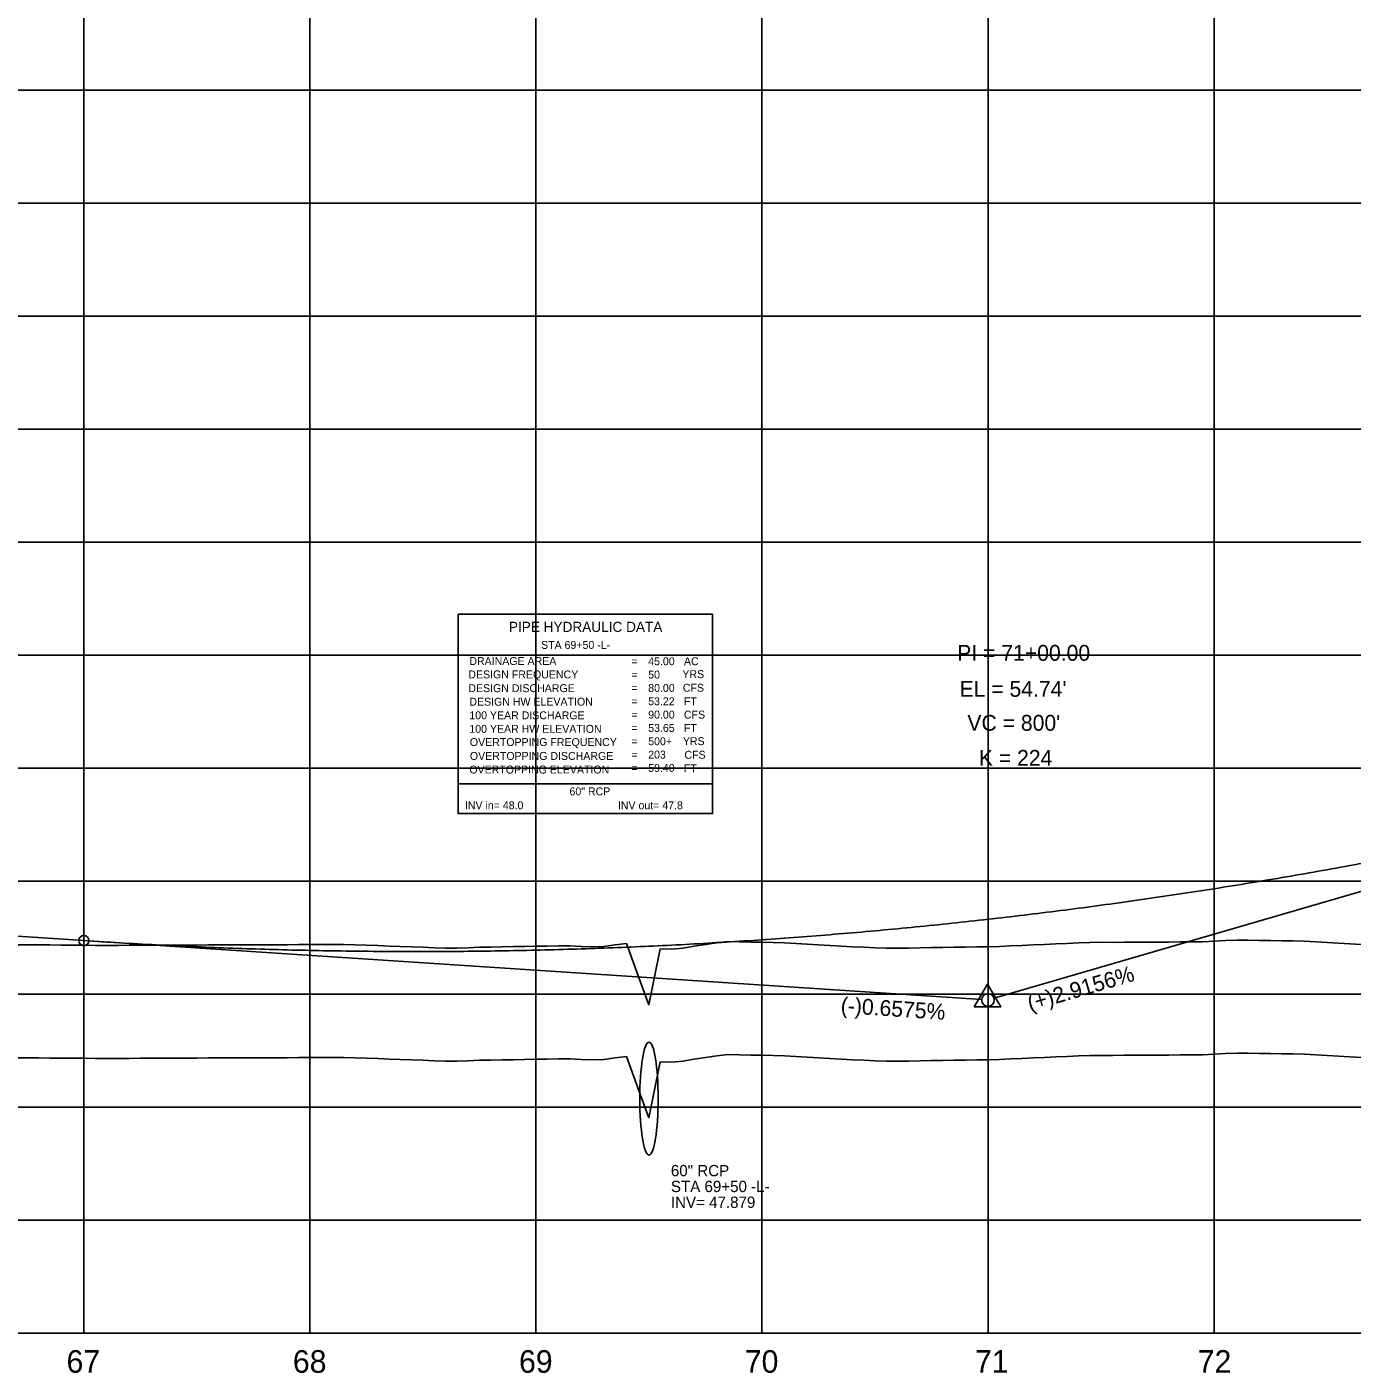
# Model space of a CAD drawing. Extents: x 2345490 to 2445302, y 465165 to 573888.
# Drawn here: x 2386996 to 2387583, y 564259 to 564854 of the extents above; entities that cross this region are included whole.
import ezdxf

# ---------------------------------------------------------------- set-up
doc = ezdxf.new("R2010")
doc.units = 0
for name, color, linetype in [('Old_Level_1', 7, 'Continuous'), ('Old_Level_2', 7, 'Continuous'), ('Old_Level_3', 7, 'Continuous'), ('Old_Level_4', 7, 'Continuous'), ('Old_Level_57', 7, 'Continuous'), ('Old_Level_62', 7, 'Continuous'), ('Old_Level_63', 7, 'Continuous')]:
    doc.layers.add(name, color=color, linetype=linetype)

msp = doc.modelspace()

# ---------------------------------------------------------------- linework, layer by layer
at = {"layer": 'Old_Level_1'}
for points in [[(2386991.5425, 564398.43875), (2386996.5425, 564398.3915), (2387001.5425, 564398.344), (2387006.5425, 564398.29675), (2387011.5425, 564398.24925), (2387016.5425, 564398.202), (2387021.5425, 564398.1545), (2387026.5425, 564398.10725), (2387031.5425, 564398.10625), (2387036.5425, 564398.1245), (2387041.5425, 564398.14725), (2387046.5425, 564398.16975), (2387051.5425, 564398.19225), (2387056.5425, 564398.21475), (2387061.5425, 564398.23725), (2387066.5425, 564398.26), (2387071.5425, 564398.2825), (2387076.5425, 564398.305), (2387081.5425, 564398.3275), (2387086.5425, 564398.346), (2387091.5425, 564398.36275), (2387096.5425, 564398.3795), (2387101.5425, 564398.3965), (2387106.5425, 564398.41325), (2387111.5425, 564398.4305), (2387116.5425, 564398.44875), (2387121.5425, 564398.46675), (2387126.5425, 564398.48475), (2387131.5425, 564398.50275), (2387136.5425, 564398.51525), (2387141.5425, 564398.39725), (2387146.5425, 564398.21075), (2387151.5425, 564398.0245), (2387156.5425, 564397.838), (2387161.5425, 564397.6515), (2387166.5425, 564397.465), (2387171.5425, 564397.27875), (2387176.5425, 564397.09225), (2387181.5425, 564396.90575), (2387186.5425, 564396.8655), (2387191.5425, 564397.10875), (2387196.5425, 564397.2735), (2387201.5425, 564397.36825), (2387206.5425, 564397.4635), (2387211.5425, 564397.55925), (2387216.5425, 564397.6555), (2387221.5425, 564397.75225), (2387226.5425, 564397.84975), (2387231.5425, 564397.9475), (2387236.5425, 564397.87625), (2387241.5425, 564397.678), (2387246.5425, 564397.47975), (2387251.5425, 564397.64325), (2387256.5425, 564398.29725), (2387261.5425, 564398.9515), (2387266.5425, 564385.04125), (2387271.5425, 564371.88275), (2387276.5425, 564396.56725), (2387281.5425, 564396.42575), (2387286.5425, 564396.9605), (2387291.5425, 564397.74525), (2387296.5425, 564398.53), (2387301.5425, 564399.3145), (2387306.5425, 564399.83925), (2387311.5425, 564399.72525), (2387316.5425, 564399.6115), (2387321.5425, 564399.498), (2387326.5425, 564399.38475), (2387331.5425, 564399.212), (2387336.5425, 564398.92425), (2387341.5425, 564398.6365), (2387346.5425, 564398.34875), (2387351.5425, 564398.06125), (2387356.5425, 564397.77375), (2387361.5425, 564397.49475), (2387366.5425, 564397.276), (2387371.5425, 564397.05725)], [(2387371.5425, 564397.05725), (2387376.5425, 564396.8385), (2387381.5425, 564396.87825), (2387386.5425, 564396.959), (2387391.5425, 564397.03975), (2387396.5425, 564397.121), (2387401.5425, 564397.2025), (2387406.5425, 564397.28425), (2387411.5425, 564397.3665), (2387416.5425, 564397.449), (2387421.5425, 564397.5425), (2387426.5425, 564397.69525), (2387431.5425, 564397.913), (2387436.5425, 564398.131), (2387441.5425, 564398.34925), (2387446.5425, 564398.56825), (2387451.5425, 564398.7875), (2387456.5425, 564399.0075), (2387461.5425, 564399.20475), (2387466.5425, 564399.36525), (2387471.5425, 564399.47475), (2387476.5425, 564399.455), (2387481.5425, 564399.4885), (2387486.5425, 564399.5215), (2387491.5425, 564399.55425), (2387496.5425, 564399.587), (2387501.5425, 564399.619), (2387506.5425, 564399.651), (2387511.5425, 564399.68275), (2387516.5425, 564399.714), (2387521.5425, 564400.02025), (2387526.5425, 564400.3435), (2387531.5425, 564400.4925), (2387536.5425, 564400.40725), (2387541.5425, 564400.32225), (2387546.5425, 564400.23725), (2387551.5425, 564400.15225), (2387556.5425, 564400.0675), (2387561.5425, 564399.98275), (2387566.5425, 564399.7175), (2387571.5425, 564399.40875), (2387576.5425, 564399.10025), (2387581.5425, 564398.7915), (2387586.5425, 564398.51675)]]:
    msp.add_lwpolyline(points, dxfattribs=at)
at = {"layer": 'Old_Level_2'}
for p, q in [((2387821.5425, 564540.556), (2387424.18275, 564424.7035)), ((2386871.5425, 564460.0965), (2387021.5425, 564450.234)), ((2387021.5425, 564450.234), (2387418.7985, 564424.11425))]:
    msp.add_line(p, q, dxfattribs=at)
msp.add_lwpolyline([(2387415.38575, 564420.8655), (2387427.12825, 564420.8655), (2387421.25725, 564430.99125)], close=True, dxfattribs=at)
for centre, radius in [((2387021.5425, 564450.234), 2.25), ((2387421.5425, 564423.934), 2.75)]:
    msp.add_circle(centre, radius, dxfattribs=at)
msp.add_spline([(2387021.5425, 564450.234), (2387037.5425, 564449.239), (2387053.5425, 564448.3585), (2387069.5425, 564447.5925), (2387085.5425, 564446.9405), (2387101.5425, 564446.403), (2387117.5425, 564445.98), (2387133.5425, 564445.67125), (2387149.5425, 564445.47675), (2387165.5425, 564445.3965), (2387181.5425, 564445.43075), (2387197.5425, 564445.57925), (2387213.5425, 564445.84225), (2387229.5425, 564446.2195), (2387245.5425, 564446.711), (2387261.5425, 564447.317), (2387277.5425, 564448.037), (2387293.5425, 564448.87175), (2387309.5425, 564449.8205), (2387325.5425, 564450.88375), (2387341.5425, 564452.0615), (2387357.5425, 564453.35325), (2387373.5425, 564454.7595), (2387389.5425, 564456.28025), (2387405.5425, 564457.91525), (2387421.5425, 564459.6645), (2387437.5425, 564461.528), (2387453.5425, 564463.506), (2387469.5425, 564465.59825), (2387485.5425, 564467.805), (2387501.5425, 564470.126), (2387517.5425, 564472.56125), (2387533.5425, 564475.11075), (2387549.5425, 564477.77475), (2387565.5425, 564480.553), (2387581.5425, 564483.44575), (2387597.5425, 564486.45275), (2387613.5425, 564489.574), (2387629.5425, 564492.80975), (2387645.5425, 564496.15975), (2387661.5425, 564499.624), (2387677.5425, 564503.20275), (2387693.5425, 564506.89575), (2387709.5425, 564510.70325), (2387725.5425, 564514.62475), (2387741.5425, 564518.661), (2387757.5425, 564522.81125), (2387773.5425, 564527.076), (2387789.5425, 564531.455), (2387805.5425, 564535.9485), (2387821.5425, 564540.556)], degree=3, dxfattribs=at)
at = {"layer": 'Old_Level_3'}
msp.add_ellipse((2387271.5425, 564380.324), major_axis=(0, 25), ratio=0.162450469, dxfattribs=at)
at = {"layer": 'Old_Level_4'}
for p, q in [((2387187.1855, 564594.62875), (2387299.6855, 564594.62875)), ((2387187.1855, 564519.62875), (2387187.1855, 564594.62875)), ((2387299.6855, 564594.62875), (2387299.6855, 564519.62875)), ((2387299.6855, 564519.62875), (2387187.1855, 564519.62875))]:
    msp.add_line(p, q, dxfattribs=at)
msp.add_lwpolyline([(2387187.1855, 564519.62875), (2387299.6855, 564519.62875), (2387299.6855, 564506.41375), (2387187.1855, 564506.41375)], close=True, dxfattribs=at)
at = {"layer": 'Old_Level_57'}
for p, q in [((2387021.54225, 564276.534), (2387021.54225, 566615.2835)), ((2387121.54225, 564276.534), (2387121.54225, 566615.2835)), ((2387221.54225, 564276.534), (2387221.54225, 566615.2835)), ((2387321.5425, 564276.534), (2387321.5425, 566615.2835)), ((2387421.5425, 564276.534), (2387421.5425, 566615.2835)), ((2387521.54225, 564276.534), (2387521.54225, 566615.2835)), ((2381271.5425, 564826.534), (2410861.12275, 564826.534)), ((2381271.54275, 564776.534), (2410861.123, 564776.534)), ((2381271.5425, 564726.534), (2410861.12275, 564726.534)), ((2381271.54275, 564676.534), (2410861.123, 564676.534)), ((2381271.5425, 564626.534), (2410861.12275, 564626.534)), ((2381271.54275, 564576.534), (2410861.123, 564576.534)), ((2381271.5425, 564526.534), (2410861.12275, 564526.534)), ((2381271.54275, 564476.534), (2410861.123, 564476.534)), ((2381271.5425, 564426.534), (2410861.12275, 564426.534)), ((2381271.54275, 564376.534), (2410861.123, 564376.534)), ((2381271.5425, 564326.534), (2410861.12275, 564326.534)), ((2381271.54275, 564276.534), (2410861.123, 564276.534))]:
    msp.add_line(p, q, dxfattribs=at)
at = {"layer": 'Old_Level_63'}
msp.add_line((2381321.5425, 564276.534), (2406689.937, 564276.534), dxfattribs=at)
for points in [[(2386991.5425, 564448.4385), (2386996.5425, 564448.39125), (2387001.5425, 564448.34375), (2387006.5425, 564448.2965), (2387011.5425, 564448.249), (2387016.5425, 564448.20175), (2387021.5425, 564448.15425), (2387026.5425, 564448.107), (2387031.5425, 564448.106), (2387036.5425, 564448.12425), (2387041.5425, 564448.147), (2387046.5425, 564448.1695), (2387051.5425, 564448.192), (2387056.5425, 564448.2145), (2387061.5425, 564448.237), (2387066.5425, 564448.25975), (2387071.5425, 564448.28225), (2387076.5425, 564448.30475), (2387081.5425, 564448.32725), (2387086.5425, 564448.34575), (2387091.5425, 564448.3625), (2387096.5425, 564448.37925), (2387101.5425, 564448.39625), (2387106.5425, 564448.413), (2387111.5425, 564448.43025), (2387116.5425, 564448.4485), (2387121.5425, 564448.4665), (2387126.5425, 564448.4845), (2387131.5425, 564448.5025), (2387136.5425, 564448.515), (2387141.5425, 564448.397), (2387146.5425, 564448.2105), (2387151.5425, 564448.02425), (2387156.5425, 564447.83775), (2387161.5425, 564447.65125), (2387166.5425, 564447.46475), (2387171.5425, 564447.2785), (2387176.5425, 564447.092), (2387181.5425, 564446.9055), (2387186.5425, 564446.86525), (2387191.5425, 564447.1085), (2387196.5425, 564447.27325), (2387201.5425, 564447.368), (2387206.5425, 564447.46325), (2387211.5425, 564447.559), (2387216.5425, 564447.65525), (2387221.5425, 564447.752), (2387226.5425, 564447.8495), (2387231.5425, 564447.94725), (2387236.5425, 564447.876), (2387241.5425, 564447.67775), (2387246.5425, 564447.4795), (2387251.5425, 564447.643), (2387256.5425, 564448.297), (2387261.5425, 564448.95125), (2387266.5425, 564435.041), (2387271.5425, 564421.8825), (2387276.5425, 564446.567), (2387281.5425, 564446.4255), (2387286.5425, 564446.96025), (2387291.5425, 564447.745), (2387296.5425, 564448.52975), (2387301.5425, 564449.31425), (2387306.5425, 564449.839), (2387311.5425, 564449.725), (2387316.5425, 564449.61125), (2387321.5425, 564449.49775), (2387326.5425, 564449.3845), (2387331.5425, 564449.21175), (2387336.5425, 564448.924), (2387341.5425, 564448.63625), (2387346.5425, 564448.3485), (2387351.5425, 564448.061), (2387356.5425, 564447.7735), (2387361.5425, 564447.4945), (2387366.5425, 564447.27575), (2387371.5425, 564447.057)], [(2387371.5425, 564447.057), (2387376.5425, 564446.83825), (2387381.5425, 564446.878), (2387386.5425, 564446.95875), (2387391.5425, 564447.0395), (2387396.5425, 564447.12075), (2387401.5425, 564447.20225), (2387406.5425, 564447.284), (2387411.5425, 564447.36625), (2387416.5425, 564447.44875), (2387421.5425, 564447.54225), (2387426.5425, 564447.695), (2387431.5425, 564447.91275), (2387436.5425, 564448.13075), (2387441.5425, 564448.349), (2387446.5425, 564448.568), (2387451.5425, 564448.78725), (2387456.5425, 564449.00725), (2387461.5425, 564449.2045), (2387466.5425, 564449.365), (2387471.5425, 564449.4745), (2387476.5425, 564449.45475), (2387481.5425, 564449.48825), (2387486.5425, 564449.52125), (2387491.5425, 564449.554), (2387496.5425, 564449.58675), (2387501.5425, 564449.61875), (2387506.5425, 564449.65075), (2387511.5425, 564449.6825), (2387516.5425, 564449.71375), (2387521.5425, 564450.02), (2387526.5425, 564450.34325), (2387531.5425, 564450.49225), (2387536.5425, 564450.407), (2387541.5425, 564450.322), (2387546.5425, 564450.237), (2387551.5425, 564450.152), (2387556.5425, 564450.06725), (2387561.5425, 564449.9825), (2387566.5425, 564449.71725), (2387571.5425, 564449.4085), (2387576.5425, 564449.1), (2387581.5425, 564448.79125), (2387586.5425, 564448.5165)]]:
    msp.add_lwpolyline(points, dxfattribs=at)

# ---------------------------------------------------------------- texts
at = {"layer": 'Old_Level_2'}
for s, height, p in [('PI = 71+00.00', 7.0000005, (2387407.8955, 564574.05325)), ("EL = 54.74'", 7.0000005, (2387408.91225, 564558.1215)), ("VC = 800'", 7.000001, (2387412.3915, 564543.0875)), ('K = 224', 7.000001, (2387417.4755, 564527.59225))]:
    msp.add_text(s, height=height, dxfattribs=at).set_placement(p)
for s, rotation, p in [('(+)2.9156%', 16.25433611, (2387440.1525, 564418.94325)), ('(-)0.6575%', 356.23821667, (2387356.22675, 564418.20675))]:
    msp.add_text(s, height=7.000001, rotation=rotation, dxfattribs=at).set_placement(p)
at = {"layer": 'Old_Level_3'}
for s, height, p in [('60" RCP', 4.999999, (2387281.242, 564345.9725)), ('STA 69+50 -L-', 4.9999995, (2387281.242, 564338.9725)), ('INV= 47.879', 4.9999995, (2387281.242, 564331.9725))]:
    msp.add_text(s, height=height, dxfattribs=at).set_placement(p)
at = {"layer": 'Old_Level_4'}
for s, height, p in [('PIPE HYDRAULIC DATA', 4.49985, (2387209.5855, 564586.80375)), ('STA 69+50 -L-', 3.4998, (2387223.80625, 564579.30325)), ('DRAINAGE AREA', 3.49995, (2387192.0855, 564572.17875)), ('=        ', 3.49995, (2387263.7355, 564572.07875)), ('45.00', 3.49995, (2387271.196, 564572.07825)), ('AC', 3.49995, (2387287.0105, 564572.07875)), ('DESIGN FREQUENCY', 3.49995, (2387191.6355, 564566.25375)), ('=        ', 3.49995, (2387263.7355, 564566.17875)), ('50', 3.49995, (2387271.196, 564566.17825)), ('YRS', 3.49995, (2387286.3105, 564566.37875)), ('DESIGN DISCHARGE', 3.49995, (2387191.6355, 564560.17875)), ('=        ', 3.49995, (2387263.7355, 564560.27875)), ('80.00', 3.49995, (2387271.196, 564560.27825)), ('CFS', 3.49995, (2387286.5355, 564560.35375)), ('DESIGN HW ELEVATION', 3.49995, (2387192.0855, 564554.17875)), ('=        ', 3.49995, (2387263.7355, 564554.37875)), ('53.22', 3.49995, (2387271.196, 564554.37825)), ('FT', 3.49995, (2387287.0105, 564554.37875)), ('100 YEAR DISCHARGE', 3.49995, (2387192.0855, 564548.17875)), ('=        ', 3.49995, (2387263.7355, 564548.47875)), ('90.00', 3.49995, (2387271.196, 564548.47825)), ('CFS', 3.49995, (2387287.0105, 564548.47875)), ('100 YEAR HW ELEVATION', 3.49995, (2387192.0855, 564542.17875)), ('=        ', 3.49995, (2387263.7355, 564542.57875)), ('53.65', 3.49995, (2387271.196, 564542.5785)), ('FT', 3.49995, (2387287.0105, 564542.57875)), ('OVERTOPPING FREQUENCY', 3.49995, (2387192.3105, 564536.32875)), ('=        ', 3.49995, (2387263.7355, 564536.67875)), ('500+', 3.49995, (2387271.196, 564536.6785)), ('YRS', 3.49995, (2387286.5355, 564536.72875)), ('OVERTOPPING DISCHARGE', 3.49995, (2387192.3105, 564530.20375)), ('=        ', 3.49995, (2387263.7355, 564530.77875)), ('203', 3.49995, (2387271.196, 564530.7785)), ('CFS', 3.49995, (2387287.2355, 564530.70375)), ('OVERTOPPING ELEVATION', 3.49995, (2387192.0855, 564524.17875)), ('=        ', 3.49995, (2387263.7355, 564524.87875)), ('59.40', 3.49995, (2387271.196, 564524.8785)), ('FT', 3.49995, (2387287.0105, 564524.67875)), ('60" RCP', 3.4998, (2387236.39125, 564514.5265)), ('INV in= 48.0', 3.4998, (2387190.118, 564508.34075)), ('INV out= 47.8', 3.4998, (2387257.79475, 564508.34075))]:
    msp.add_text(s, height=height, dxfattribs=at).set_placement(p)
at = {"layer": 'Old_Level_62'}
for s, p in [('67', (2387013.885, 564259.034)), ('68', (2387114.01075, 564259.034)), ('69', (2387214.053, 564259.034)), ('70', (2387313.929, 564259.034)), ('71', (2387415.7685, 564259.034)), ('72', (2387514.31675, 564259.034))]:
    msp.add_text(s, height=10.000001, dxfattribs=at).set_placement(p)

doc.saveas('drawing.dxf')
